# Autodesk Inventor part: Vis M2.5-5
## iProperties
Author: Flavien MARTY
Shininess: 60.0
PropertySet Name: _Private Model Information
Created: 2001-10
Part Number: Vis M2.5-5
Material: Par défaut
Document SubType Name: Modélisation
Designer: Flavien MARTY
Control State: 0
Master: False
Checked Out: False
PropertySet Name: Design Tracking Control
Density: 0.0
Volumn: 0.0
Area: 0.0
PropertySet Name: Model Information
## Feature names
1. Base1
